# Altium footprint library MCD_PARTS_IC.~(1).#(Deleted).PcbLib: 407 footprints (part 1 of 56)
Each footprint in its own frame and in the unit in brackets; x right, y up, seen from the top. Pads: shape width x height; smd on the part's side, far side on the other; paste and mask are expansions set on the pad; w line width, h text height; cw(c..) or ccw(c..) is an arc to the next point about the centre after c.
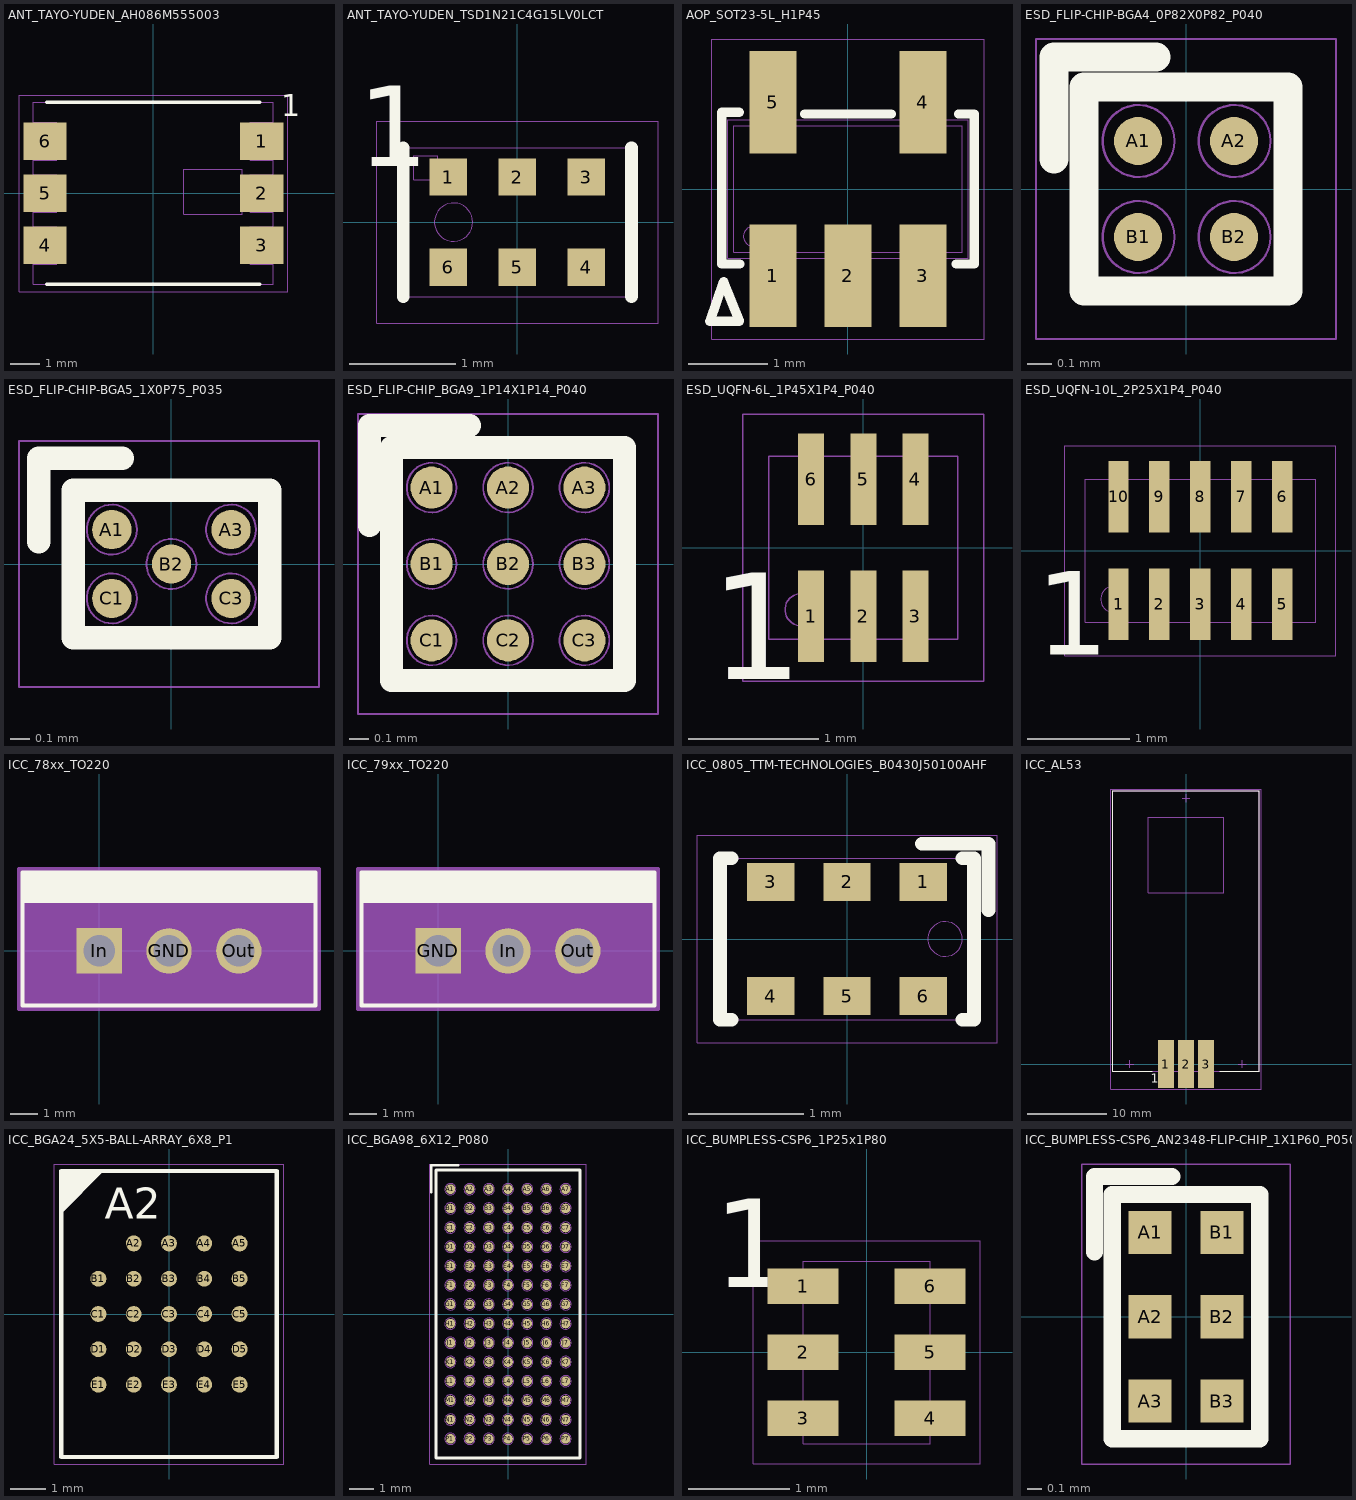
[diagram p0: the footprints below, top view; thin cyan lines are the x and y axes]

## ANT_TAYO-YUDEN_AH086M555003 [mm] "MCD-02674"
height 1.3
pads (6):
  rect 1.5x1.3 smd mask+0.05: 1(3.75,1.8) 2(3.75,-0.001) 3(3.75,-1.8) 4(-3.75,-1.8) 5(-3.75,0.001) 6(-3.75,1.8)
Top Overlay:
  lines w0.12: -3.685,-3.15 3.685,-3.15 ; -3.685,3.15 3.685,3.15
  text "1" at 4.425,2.4 h1.3
M14-Top Assembly:
  lines w0.01: -4.15,-2.45 -3.35,-2.45 -3.35,-1.15 -4.15,-1.15 ; -4.15,-0.65 -3.35,-0.65 -3.35,0.65 -4.15,0.65 ; -4.15,1.15 -3.35,1.15 -3.35,2.45 -4.15,2.45 ; 4.15,-2.45 3.35,-2.45 3.35,-1.15 4.15,-1.15 ; 4.15,-0.65 3.35,-0.65 3.35,0.65 4.15,0.65 ; 4.15,1.15 3.35,1.15 3.35,2.45 4.15,2.45 ; -4.15,-3.15 -4.15,3.15 4.15,3.15 4.15,-3.15 -4.15,-3.15 ; 1.05,-0.725 1.05,0.825 3.075,0.825 3.075,-0.725 1.05,-0.725
  text "1" at 3.525,1.325 h1.5
  text "'.Designator'" at -2,-0.5 h0.75
  text "3" at 3.45,-2.275 h1.5
  text "2" at 3.425,-0.475 h1.5
  text "4" at -4.1,1.325 h1.5
  text "5" at -4.075,-0.475 h1.5
  text "6" at -4.05,-2.275 h1.5
M16-Top Courtyard:
  lines w0.01: -4.65,-3.4 -4.65,3.4 4.65,3.4 4.65,-3.4 -4.65,-3.4
3D body: height 1.35, standoff 0.05, extent -4.125,-3.15 4.125,3.15
3D body: height 1.4, standoff 0, extent -4.15,1.15 -3.35,2.45
3D body: height 1.4, standoff 0, extent -4.15,-0.65 -3.35,0.65
3D body: height 1.4, standoff 0, extent -4.15,-2.45 -3.35,-1.15
3D body: height 1.4, standoff 0, extent 3.35,-2.45 4.15,-1.15
3D body: height 1.4, standoff 0, extent 3.35,-0.651 4.15,0.649
3D body: height 1.36, standoff 1.35, extent 1.038,-0.725 3.063,0.825
3D body: height 1.4, standoff 0, extent 3.35,1.15 4.15,2.45

## ANT_TAYO-YUDEN_TSD1N21C4G15LV0LCT [mm] "MCD-03758"
height 0.7
pads (6):
  rect 0.35x0.35 smd mask+0.05: 1(-0.65,0.425) 2(0,0.425) 3(0.65,0.425) 4(0.65,-0.425) 5(0,-0.425) 6(-0.65,-0.425)
Top Overlay:
  lines w0.12: -1.075,-0.7 -1.075,0.7 ; 1.075,-0.7 1.075,0.7
  text "1" at -1.5,0.275 h1.3
M14-Top Assembly:
  circle w0.01: c-0.6,0 r0.18
  lines w0.01: -1.075,0.625 -1.075,0.7 ; -1.075,0.7 -1.075,-0.7 1.075,-0.7 1.075,0.7 -1.075,0.7 ; -0.975,0.4 -0.975,0.625 -0.75,0.625 -0.75,0.4 ; -0.975,0.4 -0.75,0.4 ; -0.975,0.4 -0.75,0.4
  text "'.Designator'" at -2,-0.5 h0.75
M16-Top Courtyard:
  lines w0.01: -1.325,-0.95 1.325,-0.95 1.325,0.95 -1.325,0.95 -1.325,-0.95
3D body: height 0.71, standoff 0.7, extent -0.78,-0.18 -0.42,0.18
3D body: height 0.71, standoff 0.7, extent -0.975,0.4 -0.75,0.625
3D body: height 0.7, standoff 0, extent -1.075,-0.7 1.075,0.7

## AOP_SOT23-5L_H1P45 [mm]
height 1.45
pads (5):
  rect 0.6x1.3 smd mask+0.05: 1(-0.95,-1.1) 2(0,-1.1) 3(0.95,-1.1) 4(0.95,1.1) 5(-0.95,1.1)
Top Overlay:
  lines w0.12: -1.375,0.975 -1.6,0.975 -1.6,-0.95 -1.372,-0.95 ; -0.55,0.95 0.55,0.95 ; 1.372,-0.95 1.6,-0.95 1.6,0.95 1.4,0.95 ; -1.75,-1.675 -1.575,-1.175 -1.375,-1.675 -1.75,-1.675
M14-Top Assembly:
  circle w0.01: c-1.2,-0.6 r0.125
  lines w0.01: -1.15,-0.875 -1.15,-1.5 -0.75,-1.5 -0.75,-0.875 ; -1.15,0.875 -1.15,1.5 -0.75,1.5 -0.75,0.875 ; -0.2,-0.875 -0.2,-1.5 0.2,-1.5 0.2,-0.875 ; 0.75,-0.875 0.75,-1.5 1.15,-1.5 1.15,-0.875 ; 0.75,0.875 0.75,1.5 1.15,1.5 1.15,0.875 ; -1.525,-0.875 -1.525,0.875 1.525,0.875 1.525,-0.875 -1.525,-0.875 ; -1.45,-0.8 1.45,-0.8 1.45,0.8 -1.45,0.8 -1.45,-0.8
  text "'.Designator'" at -2,-0.5 h0.75
M16-Top Courtyard:
  lines w0.01: -1.725,-1.9 -1.725,1.9 1.725,1.9 1.725,-1.9 -1.725,-1.9
3D body "SOT23-5L.STEP": height 1.1, standoff 0, extent -1.5,-1.25 1.5,1.25
3D body: height 1.45, standoff 0, extent -1.524,-0.874 1.524,0.874

## ESD_FLIP-CHIP-BGA4_0P82X0P82_P040 [mm]
height 0.66
pads (4):
  round 0.2 smd paste+0 mask+0.05: A1(-0.2,0.2) A2(0.2,0.2) B1(-0.2,-0.2) B2(0.2,-0.2)
Top Overlay:
  lines w0.12: -0.55,0.125 -0.55,0.55 -0.125,0.55 ; -0.425,-0.425 0.425,-0.425 0.425,0.425 -0.425,0.425 -0.425,-0.425
M14-Top Assembly:
  circle w0.01: c0.202,-0.2 r0.15
  circle w0.01: c0.202,0.2 r0.15
  circle w0.01: c-0.198,-0.2 r0.15
  circle w0.01: c-0.198,0.2 r0.15
  lines w0.01: -0.425,-0.425 0.425,-0.425 0.425,0.425 -0.425,0.425 -0.425,-0.425
  text "A1" at -0.338,0.1 h0.3
  text "'.Designator'" at -2,-0.5 h0.75
M16-Top Courtyard:
  lines w0.01: -0.625,-0.625 0.625,-0.625 0.625,0.625 -0.625,0.625 -0.625,-0.625
3D body: height 0.67, standoff 0.66, extent -0.299,0.1 -0.1,0.3
3D body: height 0.61, standoff 0.6, extent -0.329,0.07 -0.07,0.33
3D body: height 0.66, standoff 0.23, extent -0.425,-0.425 0.425,0.425
3D body: height 0.24, standoff -0.02, extent -0.322,0.072 -0.07,0.328
3D body: height 0.24, standoff -0.02, extent 0.078,0.072 0.33,0.328
3D body: height 0.24, standoff -0.02, extent -0.322,-0.328 -0.07,-0.072
3D body: height 0.24, standoff -0.02, extent 0.078,-0.328 0.33,-0.072

## ESD_FLIP-CHIP-BGA5_1X0P75_P035 [mm] "MCD-02770"
height 0.49
pads (5):
  round 0.2 smd paste+0 mask+0.038: A1(-0.303,0.175) A3(0.303,0.175) B2(0,0) C1(-0.303,-0.175) C3(0.303,-0.175)
Top Overlay:
  lines w0.12: -0.675,0.113 -0.675,0.537 -0.25,0.537 ; -0.5,-0.375 0.5,-0.375 0.5,0.375 -0.5,0.375 -0.5,-0.375
M14-Top Assembly:
  circle w0.01: c0,0 r0.127
  circle w0.01: c0.303,-0.175 r0.127
  circle w0.01: c0.303,0.175 r0.127
  circle w0.01: c-0.303,-0.175 r0.127
  circle w0.01: c-0.303,0.175 r0.127
  lines w0.01: -0.5,-0.375 0.5,-0.375 0.5,0.375 -0.5,0.375 -0.5,-0.375
  text "A1" at -0.475,0.1 h0.3
  text "'.Designator'" at -2,-0.5 h0.75
M16-Top Courtyard:
  lines w0.01: -0.775,-0.625 0.75,-0.625 0.75,0.625 -0.775,0.625 -0.775,-0.625
3D body: height 0.5, standoff 0.49, extent -0.424,0.1 -0.225,0.3
3D body: height 0.49, standoff 0.17, extent -0.5,-0.375 0.5,0.375
3D body: height 0.23, standoff 0, extent -0.411,0.062 -0.188,0.288
3D body: height 0.23, standoff 0, extent -0.108,-0.113 0.115,0.113
3D body: height 0.23, standoff 0, extent 0.195,0.062 0.418,0.288
3D body: height 0.23, standoff 0, extent 0.195,-0.288 0.418,-0.062
3D body: height 0.23, standoff 0, extent -0.411,-0.288 -0.188,-0.062

## ESD_FLIP-CHIP_BGA9_1P14X1P14_P040 [mm] "MCD-02316"
height 0.66
pads (9):
  round 0.22 smd paste+0.02 mask+0.04: A1(-0.4,0.4) A2(0,0.4) A3(0.4,0.4) B1(-0.4,0) B2(0,0) B3(0.4,0) C1(-0.4,-0.4) C2(0,-0.4) C3(0.4,-0.4)
Top Overlay:
  lines w0.12: -0.725,0.2 -0.725,0.725 -0.2,0.725 ; -0.61,-0.61 0.61,-0.61 0.61,0.61 -0.61,0.61 -0.61,-0.61
M14-Top Assembly:
  circle w0.01: c0.4,0.4 r0.13
  circle w0.01: c0,0.4 r0.13
  circle w0.01: c-0.4,0.4 r0.13
  circle w0.01: c-0.4,0 r0.13
  circle w0.01: c0,0 r0.13
  circle w0.01: c0.4,0 r0.13
  circle w0.01: c-0.4,-0.4 r0.13
  circle w0.01: c0,-0.4 r0.13
  circle w0.01: c0.4,-0.4 r0.13
  lines w0.01: -0.585,-0.585 0.585,-0.585 0.585,0.585 -0.585,0.585 -0.585,-0.585
  text "A1" at -0.565,0.29 h0.35
  text "'.Designator'" at -2,-0.5 h0.75
M16-Top Courtyard:
  lines w0.01: -0.785,-0.785 -0.785,0.785 0.785,0.785 0.785,-0.785 -0.785,-0.785
3D body: height 0.22, standoff -0.04, extent 0.278,0.272 0.53,0.528
3D body: height 0.22, standoff -0.04, extent -0.122,0.272 0.13,0.528
3D body: height 0.67, standoff 0.66, extent -0.5,0.3 -0.3,0.5
3D body: height 0.66, standoff 0.17, extent -0.585,-0.585 0.585,0.585
3D body: height 0.22, standoff -0.04, extent -0.522,0.272 -0.27,0.528
3D body: height 0.22, standoff -0.04, extent -0.522,-0.128 -0.27,0.128
3D body: height 0.22, standoff -0.04, extent -0.122,-0.128 0.13,0.128
3D body: height 0.22, standoff -0.04, extent 0.278,-0.128 0.53,0.128
3D body: height 0.22, standoff -0.04, extent -0.522,-0.528 -0.27,-0.272
3D body: height 0.22, standoff -0.04, extent -0.122,-0.528 0.13,-0.272
3D body: height 0.22, standoff -0.04, extent 0.278,-0.528 0.53,-0.272

## ESD_UQFN-6L_1P45X1P4_P040 [mm] "MCD-03060"
height 0.5
pads (6):
  rect 0.2x0.7 smd mask+0.05: 1(-0.4,-0.525) 2(0,-0.525) 3(0.4,-0.525) 4(0.4,0.525) 5(0,0.525) 6(-0.4,0.525)
Top Overlay:
  text "1" at -1.175,-1.275 h1.4
M14-Top Assembly:
  circle w0.01: c-0.475,-0.475 r0.125
  lines w0.01: -0.725,-0.7 -0.725,0.7 0.725,0.7 0.725,-0.7 -0.725,-0.7
  text "'.Designator'" at -2,-0.5 h0.75
M16-Top Courtyard:
  lines w0.01: -0.925,-1.025 -0.925,1.025 0.925,1.025 0.925,-1.025 -0.925,-1.025
3D body: height 0.5, standoff 0, extent -0.725,-0.7 0.725,0.7
3D body: height 0.51, standoff 0.5, extent -0.624,-0.624 -0.325,-0.325

## ESD_UQFN-10L_2P25X1P4_P040 [mm] "MCD-03059"
height 0.5
pads (10):
  rect 0.2x0.7 smd mask+0.05: 1(-0.8,-0.525) 2(-0.4,-0.525) 3(0,-0.525) 4(0.4,-0.525) 5(0.8,-0.525) 6(0.8,0.525) 7(0.4,0.525) 8(0,0.525) 9(-0.4,0.525) 10(-0.8,0.525)
Top Overlay:
  text "1" at -1.606,-1.286 h1.4
M14-Top Assembly:
  circle w0.01: c-0.85,-0.475 r0.125
  lines w0.01: -1.125,-0.7 1.125,-0.7 1.125,0.7 -1.125,0.7 -1.125,-0.7
  text "'.Designator'" at -2,-0.5 h0.75
M16-Top Courtyard:
  lines w0.01: -1.325,-1.025 1.325,-1.025 1.325,1.025 -1.325,1.025 -1.325,-1.025
3D body: height 0.51, standoff 0.5, extent -0.999,-0.625 -0.7,-0.325
3D body: height 0.5, standoff 0, extent -1.125,-0.7 1.125,0.7

## ICC_78xx_TO220 [mil] "79xx Negative Voltage Regulator TO220"
pads (3):
  round 65 hole 45: GND(100,0) Out(200,0)
  rect 65x65 hole 45: In(0,0)
Top Overlay:
  rectangle: -109.06,68.5 308.27,111.81
  lines w6: -110,-78.5 -110,112.5 310,112.5 310,-78.5 -110,-78.5
M13-Bottom 3D Body:
  circle w0: c-85,0 r8
  lines w1: -105,-73.5 -105,107.5 305,107.5 305,-73.5 -105,-73.5
  lines w6: -10,0 10,0 ; 0,-10 0,10
M15-Bottom Assembly:
  region: 315,-83.5 -115,-83.5 -115,117.5 315,117.5
  lines w6: -115,-83.5 315,-83.5 315,117.5 -115,117.5 -115,-83.5
3D body "TO-220_STM.step": height 775.98, standoff -255, extent -105,-73.5 305,107.52

## ICC_79xx_TO220 [mil] "79xx Negative Voltage Regulator TO220"
pads (3):
  rect 65x65 hole 45: GND(0,0)
  round 65 hole 45: In(100,0) Out(200,0)
Top Overlay:
  rectangle: -109.06,68.5 308.27,111.81
  lines w6: -110,-78.5 -110,112.5 310,112.5 310,-78.5 -110,-78.5
M13-Bottom 3D Body:
  circle w0: c-85,0 r8
  lines w1: -105,-73.5 -105,107.5 305,107.5 305,-73.5 -105,-73.5
  lines w6: -10,0 10,0 ; 0,-10 0,10
M15-Bottom Assembly:
  region: 315,-83.5 -115,-83.5 -115,117.5 315,117.5
  lines w6: -115,-83.5 315,-83.5 315,117.5 -115,117.5 -115,-83.5
3D body "TO-220_STM.step": height 775.98, standoff -255, extent -105,-73.5 305,107.52

## ICC_0805_TTM-TECHNOLOGIES_B0430J50100AHF [mm] "MCD-03705"
height 0.7
pads (6):
  rect 0.41x0.33 smd mask+0.05: 1(0.66,0.495) 2(0,0.495) 3(-0.66,0.495) 4(-0.66,-0.495) 5(0,-0.495) 6(0.66,-0.495)
Top Overlay:
  lines w0.12: -1,-0.7 -1.1,-0.7 -1.1,0.7 -1,0.7 ; 0.65,0.825 1.225,0.825 1.225,0.25 ; 1,-0.7 1.1,-0.7 1.1,0.7 1,0.7
M14-Top Assembly:
  circle w0.01: c0.85,0 r0.15
  lines w0.01: -1.1,-0.7 -1.1,0.7 1.1,0.7 1.1,-0.7 -1.1,-0.7 ; -0.81,-0.61 -0.51,-0.61 -0.51,-0.39 -0.81,-0.39 -0.81,-0.61 ; -0.81,0.39 -0.81,0.61 -0.51,0.61 -0.51,0.39 -0.81,0.39 ; -0.15,-0.61 0.15,-0.61 0.15,-0.39 -0.15,-0.39 -0.15,-0.61 ; -0.15,0.39 -0.15,0.61 0.15,0.61 0.15,0.39 -0.15,0.39 ; 0.51,-0.61 0.81,-0.61 0.81,-0.39 0.51,-0.39 0.51,-0.61 ; 0.51,0.39 0.51,0.61 0.81,0.61 0.81,0.39 0.51,0.39
  text "4" at -0.76,-0.694 h0.45
  text "6" at 0.565,-0.692 h0.45
  text "5" at -0.096,-0.69 h0.45
  text "3" at -0.754,0.408 h0.45
  text "2" at -0.096,0.405 h0.45
  text "1" at 0.607,0.405 h0.45
  text "'.Designator'" at -2,-0.5 h0.75
M16-Top Courtyard:
  lines w0.01: -1.3,-0.9 1.3,-0.9 1.3,0.9 -1.3,0.9 -1.3,-0.9
3D body: height 0.71, standoff 0.7, extent 0.725,-0.125 0.975,0.125
3D body: height 0.7, standoff 0, extent -1.1,-0.7 1.1,0.7

## ICC_AL53 [mm] "MCD-04130"
height 12.4
pads (3):
  rect 2x6 smd mask+0.05: 1(-2.54,0) 2(0,0) 3(2.54,0)
Top Overlay:
  lines w0.12: -4.234,-0.9 -9.25,-0.9 -9.25,34.4 9.25,34.4 9.25,-0.9 4.234,-0.9
  text "1" at -4.45,-2.8 h2
M14-Top Assembly:
  lines w0.01: -7.6,0 -6.6,0 ; -7.1,-0.5 -7.1,0.5 ; -0.5,33.5 0.5,33.5 ; 0,33 0,34 ; 6.6,0 7.6,0 ; 7.1,-0.5 7.1,0.5 ; -9.25,-0.9 -9.25,34.4 9.25,34.4 9.25,-0.9 -9.25,-0.9 ; -4.75,21.6 -4.75,31.1 4.75,31.1 4.75,21.6 -4.75,21.6
  text "'.Designator'" at -1.9,5.3 h0.75
M16-Top Courtyard:
  lines w0.01: -9.5,-3.15 -9.5,34.65 9.5,34.65 9.5,-3.15 -9.5,-3.15
3D body: height 12.4, standoff 0, extent -9.25,-0.9 9.25,34.4
3D body: height 12.5, standoff 12.4, extent -4.75,21.6 4.75,31.1

## ICC_BGA24_5X5-BALL-ARRAY_6X8_P1 [mm]
height 1.2
pads (24):
  round 0.45 smd mask+0.05: A2(-1,2) A3(0,2) A4(1,2) A5(2,2) B1(-2,1) B2(-1,1) B3(0,1) B4(1,1) B5(2,1) C1(-2,0) C2(-1,0) C3(0,0) C4(1,0) C5(2,0) D1(-2,-1) D2(-1,-1) D3(0,-1) D4(1,-1) D5(2,-1) E1(-2,-2) E2(-1,-2) E3(0,-2) E4(1,-2) E5(2,-2)
Top Overlay:
  lines w0.12: -3.05,2.925 -1.925,4.05 ; -3.05,3.025 -2.025,4.05 ; -3.05,3.175 -2.175,4.05 ; -3.05,3.325 -2.325,4.05 ; -3.05,3.475 -2.475,4.05 ; -3.05,3.625 -2.625,4.05 ; -3.05,3.775 -2.775,4.05 ; -3.05,3.9 -2.9,4.05 ; -3.05,-4.05 -3.05,4.05 3.05,4.05 3.05,-4.05 -3.05,-4.05
  text "A2" at -1.825,2.4 h1.5
M14-Top Assembly:
  lines w0.01: -3.05,2.925 -1.925,4.05 -3.037,2.937 ; -3.05,-4.05 3.05,-4.05 3.05,4.05 -3.05,4.05 -3.05,-4.05
  text "'.Designator'" at -2,-0.5 h0.75
  text "A2" at -1.424,1.795 h0.75
  text "E1" at -2.304,-2.205 h0.75
  text "D1" at -2.319,-1.205 h0.75
  text "C1" at -2.36,-0.205 h0.75
  text "B1" at -2.319,0.795 h0.75
  text "A5" at 1.601,1.795 h0.75
  text "A4" at 0.594,1.82 h0.75
  text "A3" at -0.424,1.795 h0.75
M16-Top Courtyard:
  lines w0.01: -3.25,-4.25 3.25,-4.25 3.25,4.25 -3.25,4.25 -3.25,-4.25
3D body "ICC_BGA24_5X5-BALL-ARRAY_6X8_P1.STEP": height 0.96, standoff -0.04, extent -3,-4 3,4
3D body: height 1.2, standoff 0, extent -3.055,-4.055 3.055,4.055

## ICC_BGA98_6X12_P080 [mm]
height 2.11
pads (98):
  round 0.4 smd mask+0.05: A1(-2.4,5.2) A2(-1.6,5.2) A3(-0.8,5.2) A4(0,5.2) A5(0.8,5.2) A6(1.6,5.2) A7(2.4,5.2) B1(-2.4,4.4) B2(-1.6,4.4) B3(-0.8,4.4) B4(0,4.4) B5(0.8,4.4) B6(1.6,4.4) B7(2.4,4.4) C1(-2.4,3.6) C2(-1.6,3.6) C3(-0.8,3.6) C4(0,3.6) C5(0.8,3.6) C6(1.6,3.6) C7(2.4,3.6) D1(-2.4,2.8) D2(-1.6,2.8) D3(-0.8,2.8) D4(0,2.8) D5(0.8,2.8) D6(1.6,2.8) D7(2.4,2.8) E1(-2.4,2) E2(-1.6,2) E3(-0.8,2) E4(0,2) E5(0.8,2) E6(1.6,2) E7(2.4,2) F1(-2.4,1.2) F2(-1.6,1.2) F3(-0.8,1.2) F4(0,1.2) F5(0.8,1.2) F6(1.6,1.2) F7(2.4,1.2) G1(-2.4,0.4) G2(-1.6,0.4) G3(-0.8,0.4) G4(0,0.4) G5(0.8,0.4) G6(1.6,0.4) G7(2.4,0.4) H1(-2.4,-0.4) H2(-1.6,-0.4) H3(-0.8,-0.4) H4(0,-0.4) H5(0.8,-0.4) H6(1.6,-0.4) H7(2.4,-0.4) J1(-2.4,-1.2) J2(-1.6,-1.2) J3(-0.8,-1.2) J4(0,-1.2) J5(0.8,-1.2) J6(1.6,-1.2) J7(2.4,-1.2) K1(-2.4,-2) K2(-1.6,-2) K3(-0.8,-2) K4(0,-2) K5(0.8,-2) K6(1.6,-2) K7(2.4,-2) L1(-2.4,-2.8) L2(-1.6,-2.8) L3(-0.8,-2.8) L4(0,-2.8) L5(0.8,-2.8) L6(1.6,-2.8) L7(2.4,-2.8) M1(-2.4,-3.6) M2(-1.6,-3.6) M3(-0.8,-3.6) M4(0,-3.6) M5(0.8,-3.6) M6(1.6,-3.6) M7(2.4,-3.6) N1(-2.4,-4.4) N2(-1.6,-4.4) N3(-0.8,-4.4) N4(0,-4.4) N5(0.8,-4.4) N6(1.6,-4.4) N7(2.4,-4.4) P1(-2.4,-5.2) P2(-1.6,-5.2) P3(-0.8,-5.2) P4(0,-5.2) P5(0.8,-5.2) P6(1.6,-5.2) P7(2.4,-5.2)
Top Overlay:
  lines w0.12: -3.2,5.075 -3.2,6.2 -2.075,6.2 ; -3,-6 -3,6 3,6 3,-6 -3,-6
M14-Top Assembly:
  circle w0.01: c0.8,-0.4 r0.235
  circle w0.01: c0.8,-1.2 r0.235
  circle w0.01: c0.8,-2 r0.235
  circle w0.01: c0.8,-2.8 r0.235
  circle w0.01: c0.8,-3.6 r0.235
  circle w0.01: c0.8,-4.4 r0.235
  circle w0.01: c0.8,-5.2 r0.235
  circle w0.01: c0.8,0.4 r0.235
  circle w0.01: c0.8,1.2 r0.235
  circle w0.01: c0.8,2 r0.235
  circle w0.01: c0.8,2.8 r0.235
  circle w0.01: c0.8,3.6 r0.235
  circle w0.01: c0.8,4.4 r0.235
  circle w0.01: c0.8,5.2 r0.235
  circle w0.01: c1.6,-0.4 r0.235
  circle w0.01: c1.6,-1.2 r0.235
  circle w0.01: c1.6,-2 r0.235
  circle w0.01: c1.6,-2.8 r0.235
  circle w0.01: c1.6,-3.6 r0.235
  circle w0.01: c1.6,-4.4 r0.235
  circle w0.01: c1.6,-5.2 r0.235
  circle w0.01: c1.6,0.4 r0.235
  circle w0.01: c1.6,1.2 r0.235
  circle w0.01: c1.6,2 r0.235
  circle w0.01: c1.6,2.8 r0.235
  circle w0.01: c1.6,3.6 r0.235
  circle w0.01: c1.6,4.4 r0.235
  circle w0.01: c1.6,5.2 r0.235
  circle w0.01: c2.4,-1.2 r0.235
  circle w0.01: c2.4,-2 r0.235
  circle w0.01: c2.4,-2.8 r0.235
  circle w0.01: c2.4,-3.6 r0.235
  circle w0.01: c2.4,-4.4 r0.235
  circle w0.01: c2.4,-5.2 r0.235
  circle w0.01: c2.4,-0.4 r0.235
  circle w0.01: c2.4,0.4 r0.235
  circle w0.01: c2.4,1.2 r0.235
  circle w0.01: c2.4,2 r0.235
  circle w0.01: c2.4,2.8 r0.235
  circle w0.01: c2.4,3.6 r0.235
  circle w0.01: c2.4,4.4 r0.235
  circle w0.01: c2.4,5.2 r0.235
  circle w0.01: c-1.6,-0.4 r0.235
  circle w0.01: c-1.6,-1.2 r0.235
  circle w0.01: c-1.6,-2 r0.235
  circle w0.01: c-1.6,-2.8 r0.235
  circle w0.01: c-1.6,-3.6 r0.235
  circle w0.01: c-1.6,-4.4 r0.235
  circle w0.01: c-1.6,-5.2 r0.235
  circle w0.01: c-1.6,0.4 r0.235
  circle w0.01: c-1.6,1.2 r0.235
  circle w0.01: c-1.6,2 r0.235
  circle w0.01: c-1.6,2.8 r0.235
  circle w0.01: c-1.6,3.6 r0.235
  circle w0.01: c-1.6,4.4 r0.235
  circle w0.01: c-1.6,5.2 r0.235
  circle w0.01: c-0.8,-0.4 r0.235
  circle w0.01: c-0.8,-1.2 r0.235
  circle w0.01: c-0.8,-2 r0.235
  circle w0.01: c-0.8,-2.8 r0.235
  circle w0.01: c-0.8,-3.6 r0.235
  circle w0.01: c-0.8,-4.4 r0.235
  circle w0.01: c-0.8,-5.2 r0.235
  circle w0.01: c-0.8,0.4 r0.235
  circle w0.01: c-0.8,1.2 r0.235
  circle w0.01: c-0.8,2 r0.235
  circle w0.01: c-0.8,2.8 r0.235
  circle w0.01: c-0.8,3.6 r0.235
  circle w0.01: c-0.8,4.4 r0.235
  circle w0.01: c-0.8,5.2 r0.235
  circle w0.01: c0,-1.2 r0.235
  circle w0.01: c0,-2 r0.235
  circle w0.01: c0,-2.8 r0.235
  circle w0.01: c0,-3.6 r0.235
  circle w0.01: c0,-4.4 r0.235
  circle w0.01: c0,-5.2 r0.235
  circle w0.01: c0,-0.4 r0.235
  circle w0.01: c0,0.4 r0.235
  circle w0.01: c0,1.2 r0.235
  circle w0.01: c0,2 r0.235
  circle w0.01: c0,2.8 r0.235
  circle w0.01: c0,3.6 r0.235
  circle w0.01: c0,4.4 r0.235
  circle w0.01: c0,5.2 r0.235
  circle w0.01: c-2.4,-0.4 r0.235
  circle w0.01: c-2.4,-1.2 r0.235
  circle w0.01: c-2.4,-2 r0.235
  circle w0.01: c-2.4,-2.8 r0.235
  circle w0.01: c-2.4,-3.6 r0.235
  circle w0.01: c-2.4,-4.4 r0.235
  circle w0.01: c-2.4,-5.2 r0.235
  circle w0.01: c-2.4,0.4 r0.235
  circle w0.01: c-2.4,1.2 r0.235
  circle w0.01: c-2.4,2 r0.235
  circle w0.01: c-2.4,2.8 r0.235
  circle w0.01: c-2.4,3.6 r0.235
  circle w0.01: c-2.4,4.4 r0.235
  circle w0.01: c-2.4,5.2 r0.235
  lines w0.01: -3,-6 -3,6 3,6 3,-6 -3,-6
  text "'.Designator'" at -2,-0.5 h0.75
  text "A1" at -2.8,4.95 h0.75
M16-Top Courtyard:
  lines w0.01: -3.25,-6.25 -3.25,6.25 3.25,6.25 3.25,-6.25 -3.25,-6.25
3D body: height 2.12, standoff 2.11, extent -2.7,4.9 -2.1,5.5
3D body: height 2.11, standoff 0.5, extent -3,-6 3,6
3D body: height 0.52, standoff -0.04, extent -0.275,-5.475 0.275,-4.925
3D body: height 0.52, standoff -0.04, extent -1.075,-5.475 -0.525,-4.925
3D body: height 0.52, standoff -0.04, extent 2.125,-5.475 2.675,-4.925
3D body: height 0.52, standoff -0.04, extent 1.325,-5.475 1.875,-4.925
3D body: height 0.52, standoff -0.04, extent -1.875,-5.475 -1.325,-4.925
3D body: height 0.52, standoff -0.04, extent -2.675,-5.475 -2.125,-4.925
3D body: height 0.52, standoff -0.04, extent 0.525,-5.475 1.075,-4.925
3D body: height 0.52, standoff -0.04, extent 2.125,-4.675 2.675,-4.125
3D body: height 0.52, standoff -0.04, extent 1.325,-4.675 1.875,-4.125
3D body: height 0.52, standoff -0.04, extent -1.875,-4.675 -1.325,-4.125
3D body: height 0.52, standoff -0.04, extent -1.075,-4.675 -0.525,-4.125
3D body: height 0.52, standoff -0.04, extent -2.675,-4.675 -2.125,-4.125
3D body: height 0.52, standoff -0.04, extent -0.275,-4.675 0.275,-4.125
3D body: height 0.52, standoff -0.04, extent 0.525,-4.675 1.075,-4.125
3D body: height 0.52, standoff -0.04, extent 2.125,-3.875 2.675,-3.325
3D body: height 0.52, standoff -0.04, extent 1.325,-3.875 1.875,-3.325
3D body: height 0.52, standoff -0.04, extent -2.675,-3.875 -2.125,-3.325
3D body: height 0.52, standoff -0.04, extent -2.675,-3.075 -2.125,-2.525
3D body: height 0.52, standoff -0.04, extent -2.675,-2.275 -2.125,-1.725
3D body: height 0.52, standoff -0.04, extent -2.675,-1.475 -2.125,-0.925
3D body: height 0.52, standoff -0.04, extent -2.675,-0.675 -2.125,-0.125
3D body: height 0.52, standoff -0.04, extent -1.875,-3.875 -1.325,-3.325
3D body: height 0.52, standoff -0.04, extent -1.875,-3.075 -1.325,-2.525
3D body: height 0.52, standoff -0.04, extent -1.875,-2.275 -1.325,-1.725
3D body: height 0.52, standoff -0.04, extent -1.875,-1.475 -1.325,-0.925
3D body: height 0.52, standoff -0.04, extent -1.875,-0.675 -1.325,-0.125
3D body: height 0.52, standoff -0.04, extent -1.075,-3.875 -0.525,-3.325
3D body: height 0.52, standoff -0.04, extent -1.075,-0.675 -0.525,-0.125
3D body: height 0.52, standoff -0.04, extent -1.075,-3.075 -0.525,-2.525
3D body: height 0.52, standoff -0.04, extent -1.075,-2.275 -0.525,-1.725
3D body: height 0.52, standoff -0.04, extent -1.075,-1.475 -0.525,-0.925
3D body: height 0.52, standoff -0.04, extent -0.275,-3.875 0.275,-3.325
3D body: height 0.52, standoff -0.04, extent -0.275,-3.075 0.275,-2.525
3D body: height 0.52, standoff -0.04, extent -0.275,-2.275 0.275,-1.725
3D body: height 0.52, standoff -0.04, extent -0.275,-1.475 0.275,-0.925
3D body: height 0.52, standoff -0.04, extent -0.275,-0.675 0.275,-0.125
3D body: height 0.52, standoff -0.04, extent 0.525,-3.875 1.075,-3.325
3D body: height 0.52, standoff -0.04, extent 0.525,-3.075 1.075,-2.525
3D body: height 0.52, standoff -0.04, extent 0.525,-2.275 1.075,-1.725
3D body: height 0.52, standoff -0.04, extent 0.525,-1.475 1.075,-0.925
3D body: height 0.52, standoff -0.04, extent 1.325,-3.075 1.875,-2.525
3D body: height 0.52, standoff -0.04, extent 1.325,-2.275 1.875,-1.725
3D body: height 0.52, standoff -0.04, extent 1.325,-1.475 1.875,-0.925
3D body: height 0.52, standoff -0.04, extent 1.325,-0.675 1.875,-0.125
3D body: height 0.52, standoff -0.04, extent 2.125,-3.075 2.675,-2.525
3D body: height 0.52, standoff -0.04, extent 2.125,-2.275 2.675,-1.725
3D body: height 0.52, standoff -0.04, extent 2.125,-1.475 2.675,-0.925
3D body: height 0.52, standoff -0.04, extent 2.125,-0.675 2.675,-0.125
3D body: height 0.52, standoff -0.04, extent -2.675,0.125 -2.125,0.675
3D body: height 0.52, standoff -0.04, extent -2.675,0.925 -2.125,1.475
3D body: height 0.52, standoff -0.04, extent -2.675,1.725 -2.125,2.275
3D body: height 0.52, standoff -0.04, extent -2.675,2.525 -2.125,3.075
3D body: height 0.52, standoff -0.04, extent -2.675,3.325 -2.125,3.875
3D body: height 0.52, standoff -0.04, extent -1.875,0.125 -1.325,0.675
3D body: height 0.52, standoff -0.04, extent -1.875,1.725 -1.325,2.275
3D body: height 0.52, standoff -0.04, extent -1.875,0.925 -1.325,1.475
3D body: height 0.52, standoff -0.04, extent -1.875,2.525 -1.325,3.075
3D body: height 0.52, standoff -0.04, extent -1.875,3.325 -1.325,3.875
3D body: height 0.52, standoff -0.04, extent -1.079,2.528 -0.529,3.078
3D body: height 0.52, standoff -0.04, extent -1.075,0.125 -0.525,0.675
3D body: height 0.52, standoff -0.04, extent -1.075,0.925 -0.525,1.475
3D body: height 0.52, standoff -0.04, extent -1.075,1.725 -0.525,2.275
3D body: height 0.52, standoff -0.04, extent -0.279,2.528 0.271,3.078
3D body: height 0.52, standoff -0.04, extent -0.275,0.125 0.275,0.675
3D body: height 0.52, standoff -0.04, extent -0.275,0.925 0.275,1.475
3D body: height 0.52, standoff -0.04, extent -0.275,1.725 0.275,2.275
3D body: height 0.52, standoff -0.04, extent 0.521,2.528 1.071,3.078
3D body: height 0.52, standoff -0.04, extent 0.525,-0.675 1.075,-0.125
3D body: height 0.52, standoff -0.04, extent 0.525,0.125 1.075,0.675
3D body: height 0.52, standoff -0.04, extent 0.525,0.925 1.075,1.475
3D body: height 0.52, standoff -0.04, extent 0.525,1.725 1.075,2.275
3D body: height 0.52, standoff -0.04, extent 1.325,0.125 1.875,0.675
3D body: height 0.52, standoff -0.04, extent 1.325,1.725 1.875,2.275
3D body: height 0.52, standoff -0.04, extent 1.325,0.925 1.875,1.475
3D body: height 0.52, standoff -0.04, extent 1.325,2.525 1.875,3.075
3D body: height 0.52, standoff -0.04, extent 2.125,0.125 2.675,0.675
3D body: height 0.52, standoff -0.04, extent 2.125,1.725 2.675,2.275
3D body: height 0.52, standoff -0.04, extent 2.125,0.925 2.675,1.475
3D body: height 0.52, standoff -0.04, extent 2.125,2.525 2.675,3.075
3D body: height 0.52, standoff -0.04, extent -2.675,4.125 -2.125,4.675
3D body: height 0.52, standoff -0.04, extent -2.675,4.925 -2.125,5.475
3D body: height 0.52, standoff -0.04, extent -1.875,4.125 -1.325,4.675
3D body: height 0.52, standoff -0.04, extent -1.875,4.925 -1.325,5.475
3D body: height 0.52, standoff -0.04, extent -1.075,4.925 -0.525,5.475
3D body: height 0.52, standoff -0.04, extent -1.071,3.325 -0.521,3.875
3D body: height 0.52, standoff -0.04, extent -1.06,4.125 -0.51,4.675
3D body: height 0.52, standoff -0.04, extent -0.275,4.925 0.275,5.475
3D body: height 0.52, standoff -0.04, extent -0.271,3.325 0.279,3.875
3D body: height 0.52, standoff -0.04, extent -0.26,4.125 0.29,4.675
3D body: height 0.52, standoff -0.04, extent 0.525,4.925 1.075,5.475
3D body: height 0.52, standoff -0.04, extent 0.529,3.325 1.079,3.875
3D body: height 0.52, standoff -0.04, extent 0.54,4.125 1.09,4.675
3D body: height 0.52, standoff -0.04, extent 1.325,3.325 1.875,3.875
3D body: height 0.52, standoff -0.04, extent 1.325,4.125 1.875,4.675
3D body: height 0.52, standoff -0.04, extent 1.325,4.925 1.875,5.475
3D body: height 0.52, standoff -0.04, extent 2.125,3.325 2.675,3.875
3D body: height 0.52, standoff -0.04, extent 2.125,4.125 2.675,4.675
3D body: height 0.52, standoff -0.04, extent 2.125,4.925 2.675,5.475

## ICC_BUMPLESS-CSP6_1P25x1P80 [mm] "MCD-02428"
height 0.45
pads (6):
  rect 0.7x0.35 smd paste+0 mask+0.05: 1(-0.625,0.65) 2(-0.625,0) 3(-0.625,-0.65) 4(0.625,-0.65) 5(0.625,0) 6(0.625,0.65)
Top Overlay:
  text "1" at -1.507,0.357 h1.5
M14-Top Assembly:
  lines w0.01: -0.625,-0.9 -0.625,0.9 0.625,0.9 0.625,-0.9 -0.625,-0.9 ; -0.512,-0.751 -0.512,-0.551 -0.312,-0.551 -0.312,-0.751 -0.512,-0.751 ; -0.512,-0.1 -0.312,-0.1 -0.312,0.1 -0.512,0.1 -0.512,-0.1 ; -0.512,0.551 -0.312,0.551 -0.312,0.751 -0.512,0.751 -0.512,0.551 ; 0.312,-0.751 0.312,-0.551 0.512,-0.551 0.512,-0.751 0.312,-0.751 ; 0.312,-0.1 0.512,-0.1 0.512,0.1 0.312,0.1 0.312,-0.1 ; 0.312,0.551 0.512,0.551 0.512,0.751 0.312,0.751 0.312,0.551
  text "1" at -0.456,0.549 h0.3
  text "'.Designator'" at -2,-0.5 h0.75
  text "3" at -0.469,-0.751 h0.3
  text "4" at 0.342,-0.749 h0.3
  text "6" at 0.352,0.553 h0.3
  text "2" at -0.469,-0.102 h0.3
  text "5" at 0.352,-0.098 h0.3
M16-Top Courtyard:
  lines w0.01: -1.12,-1.1 1.12,-1.1 1.12,1.1 -1.12,1.1 -1.12,-1.1
3D body: height 0.46, standoff 0.45, extent -0.512,0.551 -0.313,0.751
3D body: height 0.45, standoff 0.43, extent -0.625,-0.9 0.625,0.9
3D body: height 0.43, standoff 0.03, extent -0.625,-0.9 0.625,0.9
3D body: height 0.03, standoff 0, extent 0.312,-0.751 0.512,-0.551
3D body: height 0.03, standoff 0, extent -0.512,-0.751 -0.312,-0.551
3D body: height 0.03, standoff 0, extent 0.312,-0.1 0.512,0.1
3D body: height 0.03, standoff 0, extent -0.512,-0.1 -0.312,0.1
3D body: height 0.03, standoff 0, extent 0.312,0.551 0.512,0.751
3D body: height 0.03, standoff 0, extent -0.512,0.551 -0.312,0.751

## ICC_BUMPLESS-CSP6_AN2348-FLIP-CHIP_1X1P60_P050-P0587 [mm] "MCD-02059"
height 0.45
pads (6):
  rect 0.3x0.3 smd paste+0 mask+0.05: A1(-0.25,0.587) A2(-0.25,0) A3(-0.25,-0.587) B1(0.25,0.587) B2(0.25,0) B3(0.25,-0.587)
Top Overlay:
  lines w0.12: -0.637,0.45 -0.637,0.975 -0.1,0.975 ; -0.513,-0.85 0.512,-0.85 0.512,0.85 -0.513,0.85 -0.513,-0.85
M14-Top Assembly:
  lines w0.01: -0.513,-0.813 -0.513,0.813 0.512,0.813 0.512,-0.813 -0.513,-0.813 ; -0.35,-0.687 -0.35,-0.487 -0.15,-0.487 -0.15,-0.687 -0.35,-0.687 ; -0.35,-0.1 -0.35,0.1 -0.15,0.1 -0.15,-0.1 -0.35,-0.1 ; -0.35,0.487 -0.35,0.687 -0.15,0.687 -0.15,0.487 -0.35,0.487 ; 0.15,-0.687 0.15,-0.487 0.35,-0.487 0.35,-0.687 0.15,-0.687 ; 0.15,-0.1 0.15,0.1 0.35,0.1 0.35,-0.1 0.15,-0.1 ; 0.15,0.487 0.15,0.687 0.35,0.687 0.35,0.487 0.15,0.487
  text "B1" at 0.125,0.487 h0.3
  text "B2" at 0.1,-0.1 h0.3
  text "B3" at 0.1,-0.687 h0.3
  text "A3" at -0.4,-0.687 h0.3
  text "A2" at -0.4,-0.1 h0.3
  text "A1" at -0.4,0.487 h0.3
  text "'.Designator'" at -2,-0.5 h0.75
M16-Top Courtyard:
  lines w0.01: -0.725,-1.025 0.725,-1.025 0.725,1.062 -0.725,1.062 -0.725,-1.025
3D body: height 0.46, standoff 0.45, extent -0.35,0.487 -0.151,0.687
3D body: height 0.45, standoff 0.43, extent -0.513,-0.813 0.512,0.813
3D body: height 0.43, standoff 0.03, extent -0.513,-0.813 0.512,0.813
3D body: height 0.03, standoff 0, extent 0.15,-0.687 0.35,-0.487
3D body: height 0.03, standoff 0, extent -0.35,-0.687 -0.15,-0.487
3D body: height 0.03, standoff 0, extent 0.15,-0.1 0.35,0.1
3D body: height 0.03, standoff 0, extent -0.35,-0.1 -0.15,0.1
3D body: height 0.03, standoff 0, extent 0.15,0.487 0.35,0.687
3D body: height 0.03, standoff 0, extent -0.35,0.487 -0.15,0.687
